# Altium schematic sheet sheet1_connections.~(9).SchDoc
size A3; SheetNumber: 1; SheetTotal: 3
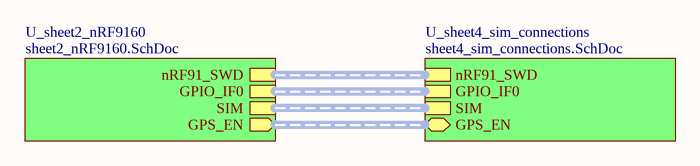
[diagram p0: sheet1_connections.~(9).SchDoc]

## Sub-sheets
U_sheet2_nRF9160 = sheet2_nRF9160.SchDoc: nRF91_SWD (harness SWD), SIM (harness SIM), GPIO_IF0 (harness GPIO_IF0), GPS_EN (out)
U_sheet4_sim_connections = sheet4_sim_connections.SchDoc: nRF91_SWD (harness SWD), GPIO_IF0 (harness GPIO_IF0), SIM (harness SIM), GPS_EN (bidir)

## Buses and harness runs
harness sheet U_sheet2_nRF9160/GPIO_IF0 = sheet U_sheet4_sim_connections/GPIO_IF0
harness sheet U_sheet2_nRF9160/GPS_EN = sheet U_sheet4_sim_connections/GPS_EN
harness sheet U_sheet2_nRF9160/nRF91_SWD = sheet U_sheet4_sim_connections/nRF91_SWD
harness sheet U_sheet2_nRF9160/SIM = sheet U_sheet4_sim_connections/SIM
